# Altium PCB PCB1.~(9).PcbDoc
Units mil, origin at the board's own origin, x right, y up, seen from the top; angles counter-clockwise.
Board outline 2228.35 x 2228.35 mil, 2 copper layers (Top Layer, Bottom Layer); 17 components, 12 nets, 58 pads, 0 vias.
Unrouted connection lines stored in the file: 14.
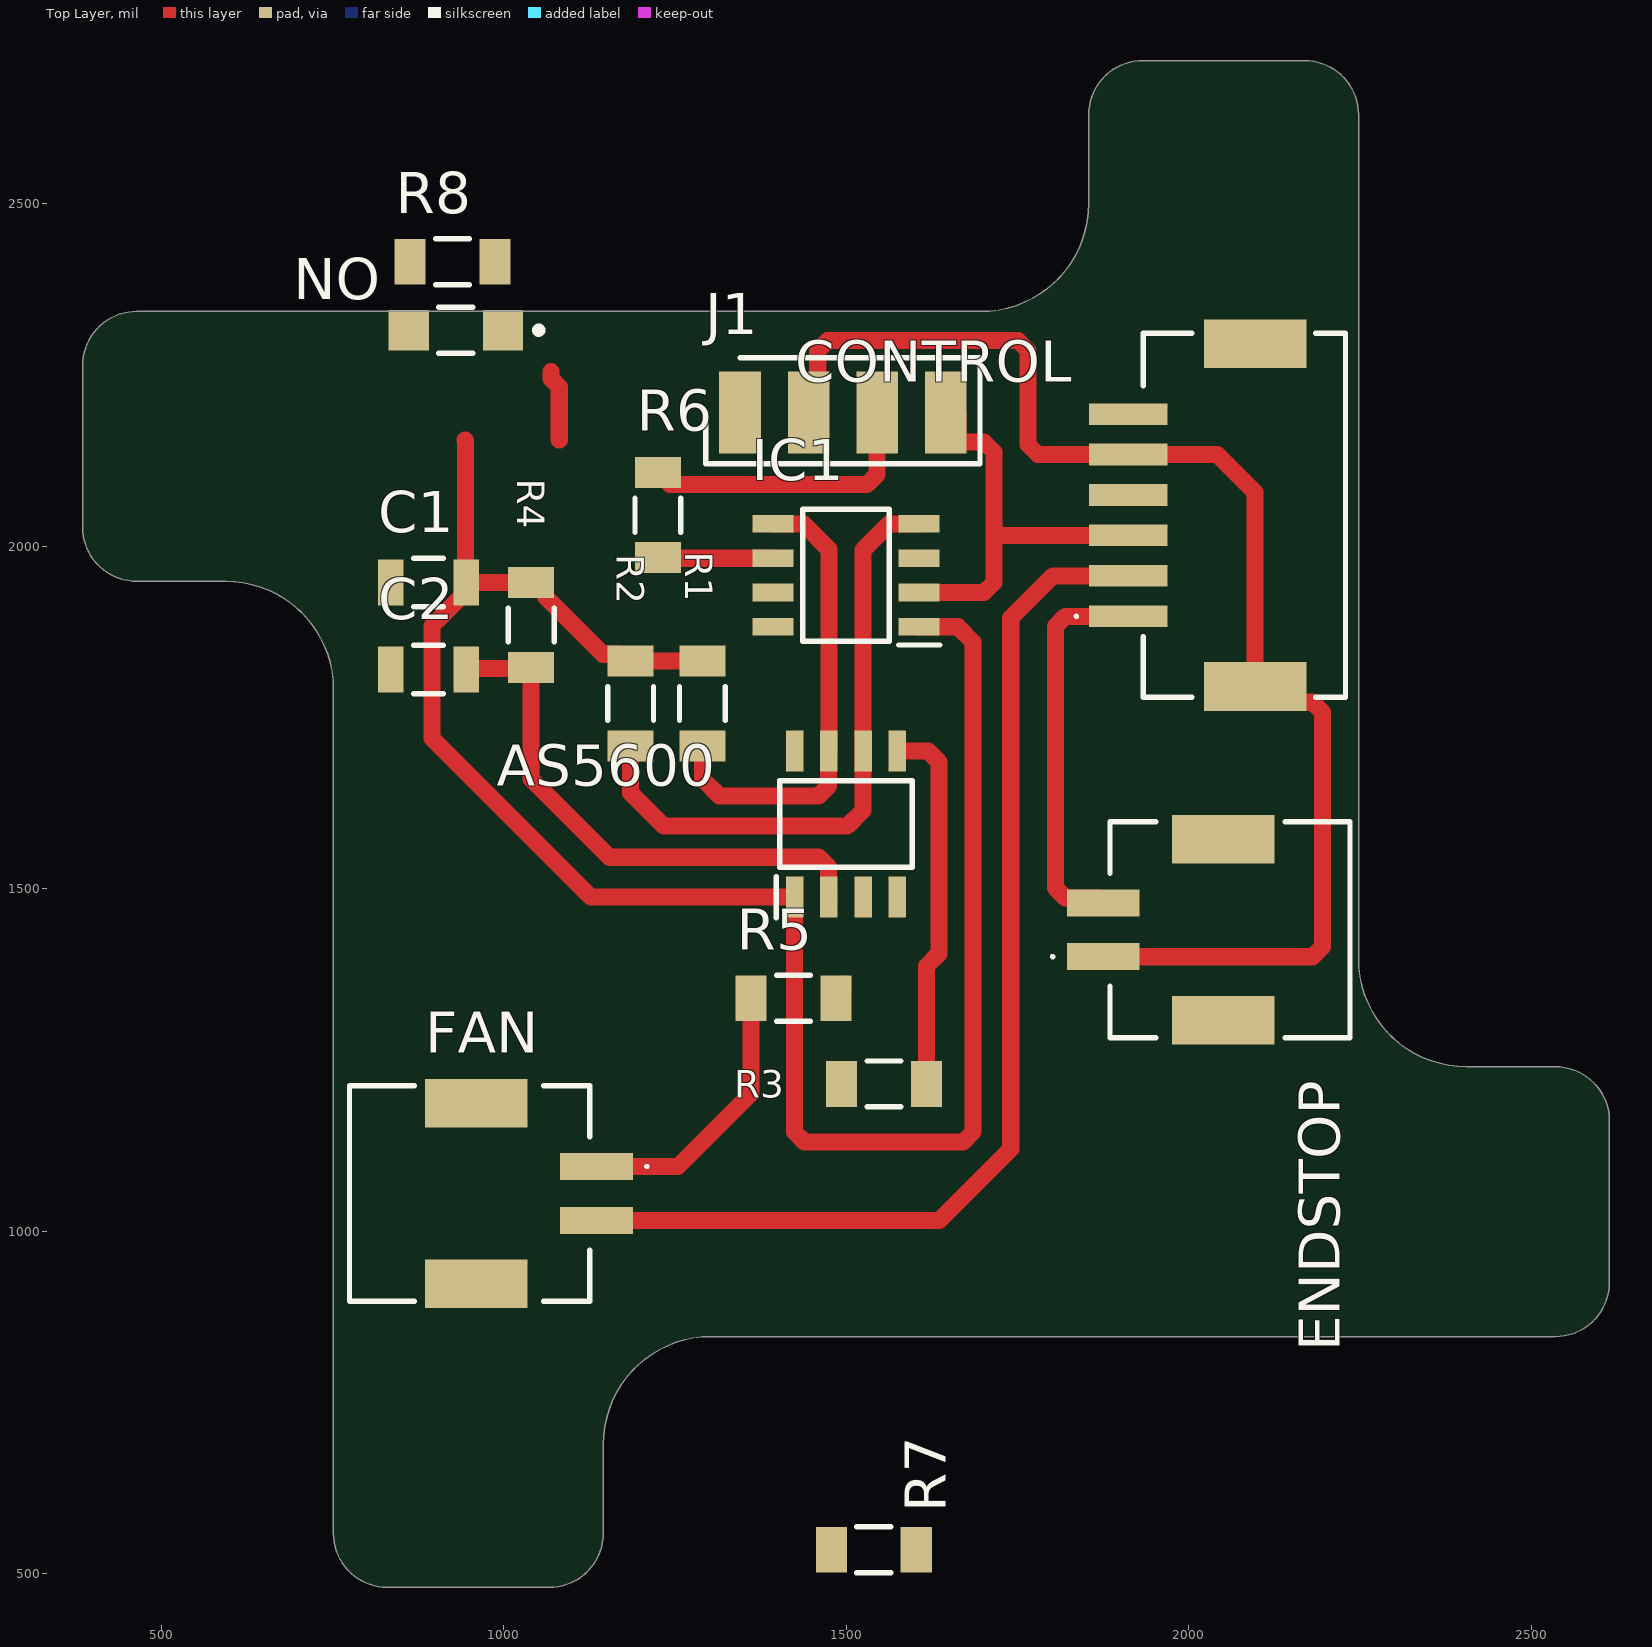
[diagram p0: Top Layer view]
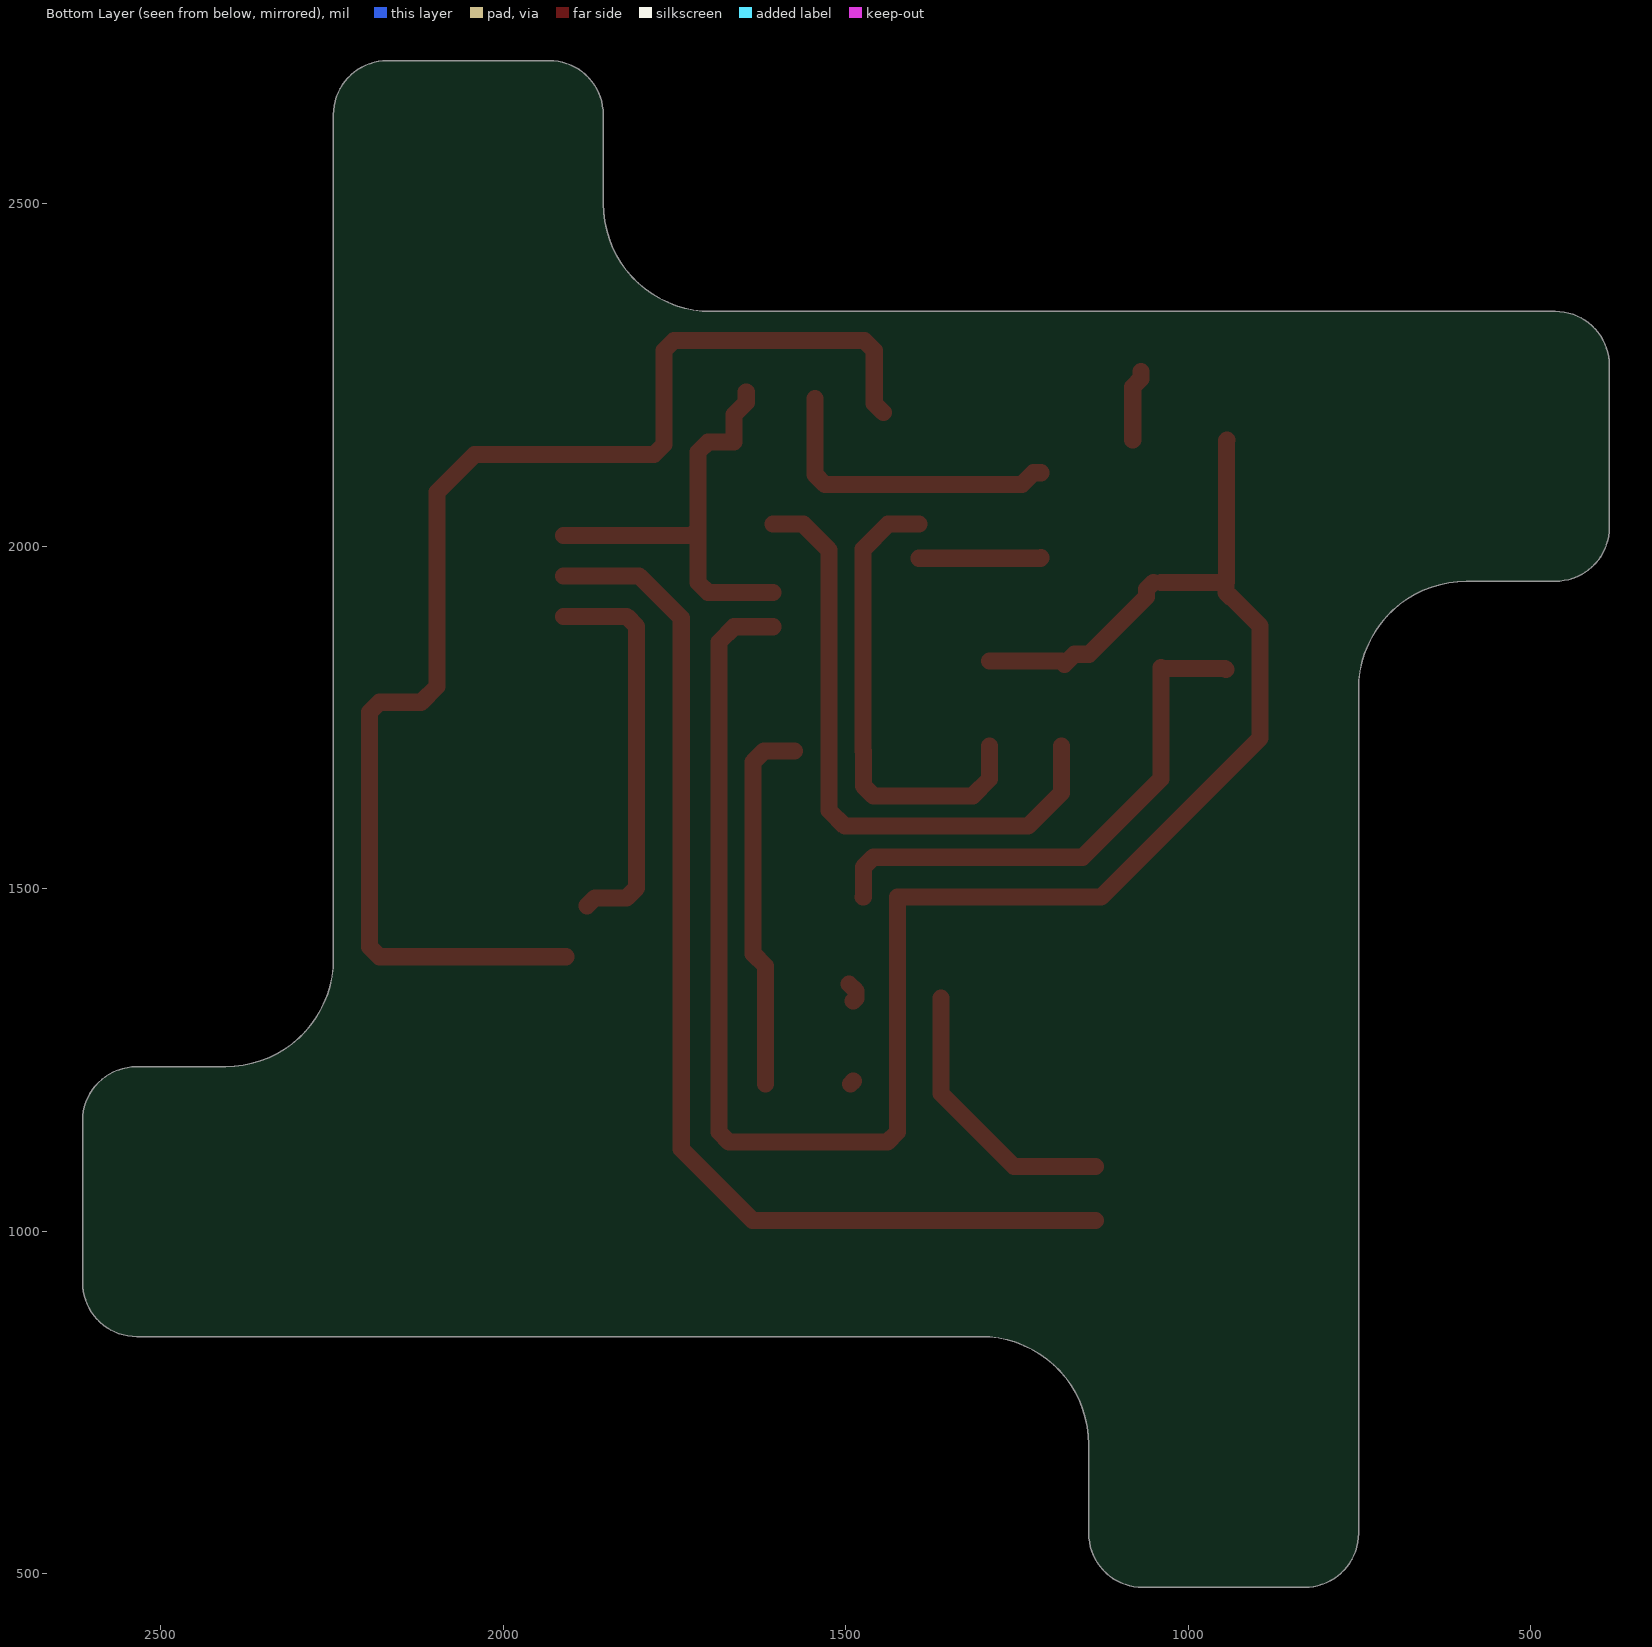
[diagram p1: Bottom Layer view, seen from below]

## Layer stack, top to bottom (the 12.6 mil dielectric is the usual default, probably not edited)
Top Solder: solder mask 0.4, Solder Resist, Dk 3.5
Top Layer: signal copper 1.4
Dielectric 1: dielectric 12.6, FR-4, Dk 4.8
Bottom Layer: signal copper 1.4
Bottom Solder: solder mask 0.4, Solder Resist, Dk 3.5

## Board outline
751.46,558.9 ccw(c830.2,558.9) 830.2,480.16 1066.42,480.16 ccw(c1066.42,558.9) 1145.16,558.9 1145.16,688.82 cw(c1302.64,688.82) 1302.64,846.3 2534.92,846.3 ccw(c2534.92,925.04) 2613.66,925.04 2613.66,1161.26 ccw(c2534.92,1161.26) 2534.92,1240 2405,1240 cw(c2405,1397.48) 2247.52,1397.48 2247.52,2629.76 ccw(c2168.78,2629.76) 2168.78,2708.5 1932.56,2708.5 ccw(c1932.56,2629.76) 1853.82,2629.76 1853.82,2499.84 cw(c1696.34,2499.84) 1696.34,2342.36 464.06,2342.36 ccw(c464.06,2263.62) 385.31,2263.62 385.31,2027.4 ccw(c464.06,2027.4) 464.06,1948.66 593.98,1948.66 cw(c593.98,1791.18) 751.46,1791.18

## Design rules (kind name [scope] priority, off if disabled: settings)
Clearance [All] p1: gap=15.75 ignorepadtopadclearanceinfootprint=FALSE
PolygonConnect [All] p1: connectstyle=Relief reliefconductorwidth=10 reliefentries=4 polygonreliefangle="90 Angle" airgapwidth=10
RoutingVias [All] p1: holewidth=28 width=50 viastyle="Through Hole" minholewidth=28 minwidth=50 maxholewidth=28 maxwidth=50
SolderMaskExpansion [All] p1: expansion=4 istentingtop=FALSE
SupplyNets "Schematic Supply Nets_2" [InNet('+5')] p1: voltage=0.000
SupplyNets "Schematic Supply Nets_1" [InNet('+3.3')] p2: voltage=0.000
SupplyNets "Schematic Supply Nets" [InNet('GND')] p3: voltage=0.000
Width [All] p1: maxlimit=25 minlimit=25 preferedwidth=25
30 further rules are at their usual default settings.

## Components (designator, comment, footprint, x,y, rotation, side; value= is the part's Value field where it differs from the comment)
AS5600 "AS5600-ASOM" SOIC127P600X175-8N 1499.49,1594.33 r90 top
C1 "C1206C102K5HACAUTO" FP-C1206C-EB-MFG 890,1947.01 r180 top value="1,000 pF"
C2 "C1206C102K5HACAUTO" FP-C1206C-EB-MFG 890,1820 r180 top value="1,000 pF"
CONTROL "C" SM06BZESSTBLFSN 2070,2045 r270 top
ENDSTOP "SM02B-PASS-TBT__LF__SN_" SM02BPASSTBTLFSN 2055,1440 r270 top
FAN "SM02B-PASS-TBT__LF__SN_" SM02BPASSTBTLFSN 955,1055 r90 top
IC1 "ATTINY412-SSF" SOIC127P600X175-8N 1499.49,1957.23 r180 top
J1 "MTSW-104-07-G-S-000" HDRV4W64P0X254_1X4_1016X254X864P 1345,2195 r180 top
ON "LTST-C150AKT" FP-LTST-C150AKT-MFG 930,2315 r180 top
R1 "CSR1206FT33L0" FP-CSR1206-MFG 1290,1770 r90 top
R2 "CSR1206FT33L0" FP-CSR1206-MFG 1185,1770 r90 top
R3 "CSR1206FT33L0" FP-CSR1206-MFG 1555,1215 r0 top
R4 "CSR1206FT33L0" FP-CSR1206-MFG 1040,1885 r270 top
R5 "CSR1206FT33L0" FP-CSR1206-MFG 1422.99,1340 r0 top
R6 "CSR1206FT33L0" FP-CSR1206-MFG 1225,2045 r90 top
R7 "CSR1206FT33L0" FP-CSR1206-MFG 1540,535 r180 top
R8 "CSR1206FT33L0" FP-CSR1206-MFG 925,2415 r180 top

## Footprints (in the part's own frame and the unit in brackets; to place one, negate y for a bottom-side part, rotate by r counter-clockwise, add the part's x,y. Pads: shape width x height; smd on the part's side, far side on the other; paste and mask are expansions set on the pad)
FP-C1206C-EB-MFG [mm]
  rect 0.95x1.7 smd paste+0 mask+0: 1(-1.4,0) 2(1.4,0)
  silkscreen extent -0.55,-0.9 0.55,0.9, body extent -2,-1 2,1, height 0.25
FP-CSR1206-MFG [mm]
  rect 1.15x1.7 smd paste+0 mask+0: 1(-1.575,0) 2(1.575,0)
  silkscreen extent -0.62,-0.85 0.62,0.85, body extent -2.25,-0.95 2.25,0.95, height 0.25
FP-LTST-C150AKT-MFG [mm]
  rect 1.5x1.5 smd paste+0 mask+0: 1(-1.75,0) 2(1.75,0)
  silkscreen extent -3.2,-0.85 0.62,0.85, body extent -2.6,-0.95 2.6,0.95, height 0.25
HDRV4W64P0X254_1X4_1016X254X864P [mil]
  rect 61.02x120 smd: 1(0,0) 2(-100,0) 3(-200,0) 4(-300,0)
  silkscreen extent -350,-80 50,75, body extent -350,-55 50,45, height 10
SM02BPASSTBTLFSN [mm]
  rect 1x2.7 smd: 1(1,-4.575) 2(-1,-4.575)
  rect 1.8x3.8 smd: 3(3.35,-0.125) 4(-3.35,-0.125)
  silkscreen extent -4,-6.5 4,4.57, body extent -4.07,-5.82 4.07,4.57, height 5.8
SM06BZESSTBLFSN [mm]
  rect 0.8x2.9 smd: 1(3.75,-4.025) 2(2.25,-4.025) 3(0.75,-4.025) 4(-0.75,-4.025) 5(-2.25,-4.025) 6(-3.75,-4.025)
  rect 1.8x3.8 smd: 7(6.35,0.675) 8(-6.35,0.675)
  silkscreen extent -6.75,-6 6.75,4.02, body extent -7.07,-5.4 7.07,4.03, height 5.9
SOIC127P600X175-8N [mm]
  rect 1.525x0.65 smd: 1(-2.712,1.905) 2(-2.712,0.635) 3(-2.712,-0.635) 4(-2.712,-1.905) 5(2.712,-1.905) 6(2.712,-0.635) 7(2.712,0.635) 8(2.712,1.905)
  silkscreen extent -3.47,-2.45 1.6,2.58, body extent -3,-2.45 3,2.45, height 1.75

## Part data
AS5600: "Integrated Circuit", Manufacturer_Name="ams OSRAM", Mouser Part Number=985-AS5600-ASOM
C1 C2: library part CMP-03020-003638-1, "C1206 1,000 pF X8R 10.00% 50 V", Capacitance="1,000 pF", Manufacturer=KEMET, Package=C1206C-EB, Temperature="-55°C to +150°C", Temperature Characteristic=X8R, Temperature Coefficient=15%, Temperature Range High=+150°C, Temperature Range Low=-55°C, Tolerance=0.1, Voltage Rating="50 V"
CONTROL: library part SM06B-ZESS-TB_LF__SN_, "Connector", Manufacturer_Name="JST (JAPAN SOLDERLESS TERMINALS)", Manufacturer_Part_Number=SM06B-ZESS-TB(LF)(SN)
ENDSTOP FAN: "Connector", Arrow Part Number="SM02B-PASS-TBT (LF)(SN)", Manufacturer_Name="JST (JAPAN SOLDERLESS TERMINALS)"
IC1: "Integrated Circuit", Manufacturer_Name=Microchip, Mouser Part Number=579-ATTINY412-SSF
J1: "Connector", Manufacturer_Name=SAMTEC
ON: library part CMP-22017-000004-1, "LED AMBER CLEAR SMD", Colour=Amber, Forward Current=30mA, Forward Voltage=2.1V, Manufacturer=Lite-On, Package=0, Power Dissipation=100mW, Reverse Voltage=5V, Temperature="-55°C to +85°C", Temperature Range High=+85°C, Temperature Range Low=-55°C
R1 R2 R3 R4 R5 R6 R7 R8: library part CMP-26527-002831-1, "General Purpose Thick Film Chip Resistor, 1206, 33mΩ, 1%, 0.5W", Case/Package=1206, Max Operating Temperature=155°C, Max Power Dissipation=500mW, Min Operating Temperature=-55°C, Package Quantity=5000, Resistance=33mR, Resistor Type="Thick Film", Temperature Coefficient=100ppm/°C, Tolerance=1%

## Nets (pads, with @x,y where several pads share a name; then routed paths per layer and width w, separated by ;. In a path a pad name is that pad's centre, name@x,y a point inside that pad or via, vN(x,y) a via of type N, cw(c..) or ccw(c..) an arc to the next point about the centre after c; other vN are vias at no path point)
+3.3: AS5600.2 C2.1 R4.2 | length 790.4
  Top Layer w25: C2.1 946.61,1821.5 1038.5,1821.5 R4.2 1040,1660 1154.17,1545.83 1459.55,1545.83 1474.19,1531.18 1474.19,1487.86 AS5600.2
+5: AS5600.1 C1.1 CONTROL.5 CONTROL.7 ENDSTOP.1 IC1.1 J1.2 ON.2 R1.2 R2.2 R4.1 | length 4832
  Top Layer w25: 943.23,2155 944.17,2154.05 944.17,1947.95 C1.1 ; R4.1 C1.1 ; R4.1@1050.83,1947.01 1060.96,1936.87 1060.96,1926.04 1144.86,1842.15 1165.85,1842.15 R2.2@1180.49,1827.5 ; R2.2 R1.2 ; J1.2 1458.19,2208.19 1458.19,2285.36 1472.83,2300 1750.36,2300 1765,2285.36 1765,2148.23 1779.64,2133.58 2041.42,2133.58 2096.57,2078.43 CONTROL.7 2119.51,1772.07 2180.36,1772.07 2195,1757.42 2195,1415.23 2180.36,1400.59 ENDSTOP.1@1908.3,1400.59 ; IC1.1 1662.77,1882.23 1685,1860 1685,1144.64 1670.36,1130 1439.13,1130 1424.49,1144.64 AS5600.1 1127.44,1487.56 895,1720 895,1883.37 937.68,1926.04 938.92,1926.04 945.12,1932.24 C1.1
END: CONTROL.1 ENDSTOP.2 | length 577.4
  Top Layer w25: ENDSTOP.2@1877.39,1475 1865.84,1486.56 1819.64,1486.56 1805,1501.2 1805,1882.72 1819.64,1897.36 CONTROL.1
FAN: CONTROL.2 FAN.2 | length 1620.1
  Top Layer w25: FAN.2 1635.63,1015.63 1740,1120 1740,1895 1801.42,1956.42 CONTROL.2
GND: AS5600.4 C1.2 C2.2 CONTROL.4 CONTROL.6 FAN.1 IC1.8 J1.1 R3.1 R5.1 R5.2 R8.2 | length 441.1
  Top Layer w25: FAN.1 1254.37,1094.37 1360.98,1200.98 R5.1 ; R5.2 R5.2@1489,1336 ; R5.2@1485,1344.43 1485,1350.83 R5.2@1495.14,1360.96 ; R3.1@1489,1219 R3.1
NetAS5600_5: AS5600.5 R3.2 | length 544.6
  Top Layer w25: AS5600.5 1618.9,1701.1 1635,1685 1635,1405 1617.01,1387.01 R3.2
NetIC1_6: IC1.6 R6.1 | length 178
  Top Layer w25: R6.1@1215,1982.99 1215.76,1982.23 IC1.6
NetON_1: ON.1 R8.1 | length 104.9
  Top Layer w25: 1069.13,2255 1069.13,2244.17 1081.02,2232.28 1081.02,2155
SCL: AS5600.7 IC1.5 R1.1 | length 691
  Top Layer w25: R1.1 1290,1660 1314.57,1635.43 1459.55,1635.43 1474.19,1650.07 1474.19,1700.81 AS5600.7 1474.49,1995.51 1438.07,2031.93 1393.01,2031.93 IC1.5
SDA: AS5600.6 IC1.4 R2.1 | length 914.7
  Top Layer w25: R2.1 1185,1640 1233.79,1591.21 1501.21,1591.21 1524.19,1614.19 1524.19,1700.81 AS5600.6 1524.49,1994.49 1561.93,2031.93 1605.96,2031.93 IC1.4
TX: CONTROL.3 IC1.2 J1.4 | length 644.5
  Top Layer w25: IC1.2 1700.72,1932.23 1715.37,1946.87 1715.37,2024.63 ; J1.4@1645,2225 1645,2209.64 1663.01,2191.63 1663.01,2151.81 1700.72,2151.81 1715.37,2137.17 1715.37,2024.63 ; CONTROL.3 1724.53,2015.47 1715.37,2024.63
UPDI: J1.3 R6.2 | length 453.5
  Top Layer w25: R6.2@1215,2107.01 1225.83,2107.01 1242.83,2090 1530.36,2090 1545,2104.64 J1.3@1545,2215
pads on no net: AS5600.3 AS5600.8 CONTROL.8 ENDSTOP.3 ENDSTOP.4 FAN.3 FAN.4 IC1.3 IC1.7 R7.1 R7.2

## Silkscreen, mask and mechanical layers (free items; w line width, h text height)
Mechanical 1:
  circle w1: c2495.55,952.6 r62.99
  circle w0.5: c503.43,2236.06 r62.99
  circle w0.5: c857.76,598.27 r62.99
  circle w0.5: c2141.22,2590.39 r62.99
  lines w0.5: 385.31,2027.4 ccw(c464.06,2027.4) 464.06,1948.66 593.98,1948.66 cw(c593.98,1791.18) 751.46,1791.18 751.46,558.9 ccw(c830.2,558.9) 830.2,480.16 1066.42,480.16 ccw(c1066.42,558.9) 1145.16,558.9 1145.16,688.82 cw(c1302.64,688.82) 1302.64,846.3 2534.92,846.3 ccw(c2534.92,925.04) 2613.66,925.04 2613.66,1161.26 ccw(c2534.92,1161.26) 2534.92,1240 2405,1240 cw(c2405,1397.48) 2247.52,1397.48 2247.52,2629.76 ccw(c2168.78,2629.76) 2168.78,2708.5 1932.56,2708.5 ccw(c1932.56,2629.76) 1853.82,2629.76 1853.82,2499.84 cw(c1696.34,2499.84) 1696.34,2342.36 464.06,2342.36 ccw(c464.06,2263.62) 385.31,2263.62 385.32,2027.4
